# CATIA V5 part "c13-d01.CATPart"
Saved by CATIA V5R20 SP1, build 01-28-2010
Part number: Part1
Bounding box of the stored display mesh (mm): x -175 to 175, y -250 to 250, z -108 to 0
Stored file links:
  D:\v5_r20\psrt_files_downloaded\c13-catia-v5r20-prt\Figure 13-8\c13-d01.CATPart
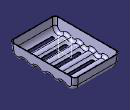
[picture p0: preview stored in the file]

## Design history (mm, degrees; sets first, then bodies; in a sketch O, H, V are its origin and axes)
Set1
  Plane1: type Offset, RefPlane yz-plane, Offset 120
  Plane2: type Offset, RefPlane xy-plane, Offset 108, reversed
Body1 (main body)
  Sketch1 on yz-plane, origin (0, 0, 0), H (0, 1, 0), V (0, 0, 1)
    line L1 (-250, 0) -> (250, 0)
    point P1 (-250, 0)
    point P2 (250, 0)
    line L2 (-250, 0) -> (-250, -100)
    point P3 (-250, -50)
    construction arc A1 centre (-200, -50) radius 50 from (-250, -50) to (-161.5385, -81.9486) ccw
    point P4 (-200, -50)
    construction arc A2 centre (-150, -91.5331) radius 15 from (-161.5385, -81.9486) to (-138.4615, -81.9486) cw
    construction arc A3 centre (-100, -50) radius 50 from (-138.4615, -81.9486) to (-61.5385, -81.9486) ccw
    point P8 (-100, -50)
    construction arc A4 centre (-50, -91.5331) radius 15 from (-61.5385, -81.9486) to (-38.4615, -81.9486) cw
    point P10 (-50, -91.5331)
    construction arc A5 centre (0, -50) radius 50 from (-38.4615, -81.9486) to (38.4615, -81.9486) ccw
    point P12 (0, -50)
    construction arc A6 centre (50, -91.5331) radius 15 from (38.4615, -81.9486) to (61.5385, -81.9486) cw
    point P14 (50, -91.5331)
    construction arc A7 centre (100, -50) radius 50 from (61.5385, -81.9486) to (138.4615, -81.9486) ccw
    point P16 (100, -50)
    construction arc A8 centre (150, -91.5331) radius 15 from (138.4615, -81.9486) to (161.5385, -81.9486) cw
    construction arc A9 centre (200, -50) radius 50 from (161.5385, -81.9486) to (250, -50) ccw
    point P21 (250, -50)
    line L3 (250, -100) -> (250, 0)
    construction line L4 (200, -50) -> (-159.8058, -50)
    construction line L5 (-150, -91.5331) -> (150, -91.5331)
    line L6 (-250, -100) -> (250, -100)
    length L1 = 500
    radius A1 = 50
    radius A3 = 50
    radius A5 = 50
    radius A7 = 50
    radius A9 = 50
    distance P2 V = 250
    radius A2 = 15
    radius A4 = 15
    radius A6 = 15
    radius A8 = 15
    coincidence: P1 H, L4 P4, P16 L4, P12 L4, P8 L4, P10 L5, P14 L5, P3 L2, P21 L3
    horizontal: L1 H, L4 H, L5 H, L6 H
    vertical: L2 V, L3 V
    tangency: A1 L1, A1 L2, A2 A1, A3 A2, A4 A3, A5 A4, A6 A5, A7 A6, A8 A7, A9 A8, L3 A9, L6 A1
  Pad1: profile Sketch1, direction (1, 0, 0), length 175, mirrored extent
  Draft1: PullDir face of Pad1, Angle -5, SupportToDraft (face of Pad1; face of Pad1; face of Pad1; face of Pad1), Neutral face of Pad1
  Sketch2 on yz-plane, origin (0, 0, 0), H (0, 1, 0), V (0, 0, 1)
    point P1 (-245.2443, -54.3578)
    arc A1 centre (-195.4346, -50) radius 50 from (-245.2443, -54.3578) to (-162.8621, -87.9346) ccw
    arc A2 centre (-146.5759, -106.902) radius 25 from (-162.8621, -87.9346) to (-130.2897, -87.9346) cw
    arc A3 centre (-97.7173, -50) radius 50 from (-130.2897, -87.9346) to (-65.1449, -87.9346) ccw
    point P6 (-97.7173, -50)
    arc A4 centre (-48.8586, -106.902) radius 25 from (-65.1449, -87.9346) to (-32.5724, -87.9346) cw
    point P8 (-48.8586, -106.902)
    arc A5 centre (0, -50) radius 50 from (-32.5724, -87.9346) to (32.5724, -87.9346) ccw
    point P10 (0, -50)
    arc A6 centre (48.8586, -106.902) radius 25 from (32.5724, -87.9346) to (65.1449, -87.9346) cw
    point P12 (48.8586, -106.902)
    arc A7 centre (97.7173, -50) radius 50 from (65.1449, -87.9346) to (130.2897, -87.9346) ccw
    point P14 (97.7173, -50)
    arc A8 centre (146.5759, -106.902) radius 25 from (130.2897, -87.9346) to (162.8621, -87.9346) cw
    arc A9 centre (195.4346, -50) radius 50 from (162.8621, -87.9346) to (245.2443, -54.3578) ccw
    point P19 (245.2443, -54.3578)
    reference projected line E1 (241.2511, -100) -> (250, 0) from edge [face of Pad1 | face of Pad1]
    reference projected line E2 (241.2511, -100) -> (250, 0) from edge [face of Pad1 | face of Pad1]
    reference projected line E3 (-250, 0) -> (-241.2511, -100) from edge [face of Pad1 | face of Pad1]
    reference projected line E4 (-250, 0) -> (-241.2511, -100) from edge [face of Pad1 | face of Pad1]
    reference projected line E5 (241.2511, -100) -> (-241.2511, -100) from edge [face of Pad1 | face of Pad1]
    reference projected line E6 (241.2511, -100) -> (-241.2511, -100) from edge [face of Pad1 | face of Pad1]
    reference projected line E7 (241.2511, -100) -> (-241.2511, -100) from edge [face of Pad1 | face of Pad1]
    reference projected line E8 (241.2511, -100) -> (-241.2511, -100) from edge [face of Pad1 | face of Pad1]
    reference projected line E9 (241.2511, -100) -> (-241.2511, -100) from edge [face of Pad1 | face of Pad1]
    construction line L1 (-195.4346, -50) -> (195.4346, -50)
    axis line L2 (146.5759, -106.902) -> (-146.5759, -106.902)
    radius A1 = 50
    radius A2 = 25
    radius A4 = 25
    radius A6 = 25
    radius A8 = 25
    tangency: A2 A1, A3 A2, A4 A3, A5 A4, A6 A5, A7 A6, A8 A7, A9 A8, A9 E1, A1 E4, A1 E5, A3 E6, A5 E7, A7 E8, A9 E9
    coincidence: P19 E2, P1 E3, P6 L1, P10 L1, P14 L1, P8 L2, L2 P12
    horizontal: L1 H, L2 H
  Pocket1: profile Sketch2, direction (-1, 0, 0), length 175, opposite side through (limit type 3)
  Fillet1: radius 25, on 2 edges
  Shell1: IntOffset 5, Face face of Pad1, ExtOffset 0
  Sketch3 on xy-plane, origin (0, 0, 0), H (1, 0, 0), V (0, 1, 0)
    construction line L1 (-105, -200) -> (105, -200)
    point P2 (105, -200)
    line L2 (-105, -188) -> (105, -188)
    line L3 (105, -212) -> (-105, -212)
    arc A1 centre (105, -200) radius 12 from (105, -188) to (105, -212) cw
    arc A2 centre (-105, -200) radius 12 from (-105, -212) to (-105, -188) cw
    reference projected line E1 (-175, -250) -> (175, -250) from edge [face of Pad1 | face of Pad1]
    reference projected line E2 (175, -250) -> (175, 250) from edge [face of Pad1 | face of Pad1]
    distance L1 E1 = 50
    distance E2 P2 = 70
    radius A1 = 12
    length L1 = 210
    horizontal: L1 H
    tangency: A1 L2, A2 L2, A1 L3, A2 L3
    parallelism: L1 L2
  Pocket2: profile Sketch3, direction (0, 0, -1), through (limit type 3)
  RectPattern1: of Pocket2, direction 1 instances 5, spacing 101, along edge [face of Pad1 | face of Pad1]
  Sketch4 on Plane2, origin (0, 0, -108), H (1, 0, 0), V (0, 1, 0)
    circle A1 centre (130, -200) radius 5
    point P1 (130, -200)
    reference projected line E1 (175, -250) -> (175, 250) from edge [face of Pad1 | face of Pad1]
    reference projected line E2 (-175, -250) -> (175, -250) from edge [face of Pad1 | face of Pad1]
    distance P1 E1 = 45
    distance P1 E2 = 50
    radius A1 = 5
  Pad2: profile Sketch4, direction (0, 0, 1), up to the existing solid (limit type 2)
  Draft2: PullDir face of Pad1, Angle -5, SupportToDraft face of Pad2, Neutral face of Pad2
  Fillet2: radius 2, on edge [face of Pad2 | face of Pad2]
  RectPattern2: of Pad2, Sketch4, Draft2, Fillet2, direction 1 instances 2, spacing 402, along edge [face of Pad1 | face of Pad1], direction 2 instances 2, spacing 260, along edge [face of Pad1 | face of Pad1] reversed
